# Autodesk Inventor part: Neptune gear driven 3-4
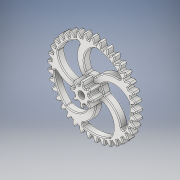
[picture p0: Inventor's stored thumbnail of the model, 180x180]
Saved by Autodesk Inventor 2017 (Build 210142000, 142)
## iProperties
Created: 2016-07
Part Number: Neptune gear driven 3-4
Material: Generic
Document SubType Name: Modeling
Designer: Stan
Density: 1 g/cm^3
Appearance: White
Author: Stan
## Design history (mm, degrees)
sketch "Sketch1" dims "d5" = 11.1125
  geometry: A1 r 17.728 centre (35.496, -7.809) between (28.667, -24.17) and (32.765, -25.326); A2 r 17.728 centre (35.496, -7.809) between (28.667, -24.17) and (32.765, -25.326); A3 r 17.728 centre (12.255, -34.216) between (29.283, -29.283) and (27.615, -25.365); A4 r 17.728 centre (12.255, -34.216) between (29.283, -29.283) and (27.615, -25.365); A5 r 17.728 centre (36.305, -1.698) between (32.339, -18.978) and (36.574, -19.425); A6 r 17.728 centre (36.305, -1.698) between (32.339, -18.978) and (36.574, -19.425); A7 r 17.728 centre (17.861, -31.653) between (33.811, -23.913) and (31.505, -20.333); A8 r 17.728 centre (17.861, -31.653) between (33.811, -23.913) and (31.505, -20.333); A9 r 17.728 centre (36.07, 4.462) between (35.082, -13.239) and (39.331, -12.964); A10 r 17.728 centre (36.07, 4.462) between (35.082, -13.239) and (39.331, -12.964); A11 r 17.728 centre (22.953, -28.179) between (37.366, -17.855) and (34.488, -14.716); A12 r 17.728 centre (22.953, -28.179) between (37.366, -17.855) and (34.488, -14.716); A13 r 17.728 centre (34.797, 10.493) between (36.814, -7.12) and (40.956, -6.131); A14 r 17.728 centre (34.797, 10.493) between (36.814, -7.12) and (40.956, -6.131); A15 r 17.728 centre (27.386, -23.895) between (39.846, -11.283) and (36.479, -8.676); A16 r 17.728 centre (27.386, -23.895) between (39.846, -11.283) and (36.479, -8.676); A17 r 17.728 centre (32.523, 16.223) between (37.488, -0.796) and (41.403, 0.879); A18 r 17.728 centre (32.523, 16.223) between (37.488, -0.796) and (41.403, 0.879); A19 r 17.728 centre (31.03, -18.923) between (41.179, -4.387) and (37.421, -2.386); A20 r 17.728 centre (31.03, -18.923) between (41.179, -4.387) and (37.421, -2.386); A21 r 17.728 centre (29.313, 21.486) between (37.083, 5.551) and (40.659, 7.863); A22 r 17.728 centre (29.313, 21.486) between (37.083, 5.551) and (40.659, 7.863); A23 r 17.728 centre (33.782, -13.407) between (41.328, 2.635) and (37.286, 3.972); A24 r 17.728 centre (33.782, -13.407) between (41.328, 2.635) and (37.286, 3.972); A25 r 17.728 centre (25.261, 26.131) between (35.612, 11.738) and (38.745, 14.622); A26 r 17.728 centre (25.261, 26.131) between (35.612, 11.738) and (38.745, 14.622); A27 r 17.728 centre (35.561, -7.505) between (40.289, 9.582) and (36.078, 10.216); A28 r 17.728 centre (35.561, -7.505) between (40.289, 9.582) and (36.078, 10.216); A29 r 17.728 centre (20.481, 30.024) between (33.116, 17.588) and (35.717, 20.959); A30 r 17.728 centre (20.481, 30.024) between (33.116, 17.588) and (35.717, 20.959); A31 r 17.728 centre (36.318, -1.387) between (38.09, 16.253) and (33.832, 16.167); A32 r 17.728 centre (36.318, -1.387) between (38.09, 16.253) and (33.832, 16.167); A33 r 17.728 centre (15.112, 33.054) between (29.667, 22.932) and (31.661, 26.694); A34 r 17.728 centre (15.112, 33.054) between (29.667, 22.932) and (31.661, 26.694); A35 r 17.728 centre (36.03, 4.771) between (34.795, 22.456) and (30.614, 21.652); A36 r 17.728 centre (36.03, 4.771) between (34.795, 22.456) and (30.614, 21.652); A37 r 17.728 centre (9.309, 35.132) between (25.365, 27.615) and (26.694, 31.661); A38 r 17.728 centre (9.309, 35.132) between (25.365, 27.615) and (26.694, 31.661); A39 r 17.728 centre (34.705, 10.791) between (30.499, 28.014) and (26.514, 26.514); A40 r 17.728 centre (34.705, 10.791) between (30.499, 28.014) and (26.514, 26.514); A41 r 17.728 centre (32.383, 16.501) between (25.326, 32.765) and (21.652, 30.614); A42 r 17.728 centre (32.383, 16.501) between (25.326, 32.765) and (21.652, 30.614); A43 r 17.728 centre (9.007, 35.211) between (-7.863, 40.659) and (-8.676, 36.479); A44 r 17.728 centre (-25.035, 26.347) between (-10.216, 36.078) and (-12.964, 39.331); A45 r 17.728 centre (2.927, 36.227) between (-14.622, 38.745) and (-14.716, 34.488); A46 r 17.728 centre (-29.128, 21.737) between (-16.167, 33.832) and (-19.425, 36.574); A47 r 17.728 centre (-3.238, 36.2) between (-20.959, 35.717) and (-20.333, 31.505); A48 r 17.728 centre (-32.383, 16.501) between (-21.652, 30.614) and (-25.326, 32.765); A49 r 17.728 centre (-9.309, 35.132) between (-26.694, 31.661) and (-25.365, 27.615); A50 r 17.728 centre (-34.705, 10.791) between (-26.514, 26.514) and (-30.499, 28.014); A51 r 17.728 centre (-15.112, 33.054) between (-31.661, 26.694) and (-29.667, 22.932); A52 r 17.728 centre (-36.03, 4.771) between (-30.614, 21.652) and (-34.795, 22.456); A53 r 17.728 centre (-20.481, 30.024) between (-35.717, 20.959) and (-33.116, 17.588); A54 r 17.728 centre (-36.318, -1.387) between (-33.832, 16.167) and (-38.09, 16.253); A55 r 17.728 centre (-25.261, 26.131) between (-38.745, 14.622) and (-35.612, 11.738); A56 r 17.728 centre (-35.561, -7.505) between (-36.078, 10.216) and (-40.289, 9.582); A57 r 17.728 centre (-29.313, 21.486) between (-40.659, 7.863) and (-37.083, 5.551); A58 r 17.728 centre (-33.782, -13.407) between (-37.286, 3.972) and (-41.328, 2.635); A59 r 17.728 centre (-32.523, 16.223) between (-41.403, 0.879) and (-37.488, -0.796); A60 r 17.728 centre (-31.03, -18.923) between (-37.421, -2.386) and (-41.179, -4.387); A61 r 17.728 centre (-34.797, 10.493) between (-40.956, -6.131) and (-36.814, -7.12); A62 r 17.728 centre (-27.386, -23.895) between (-36.479, -8.676) and (-39.846, -11.283); A63 r 17.728 centre (-36.07, 4.462) between (-39.331, -12.964) and (-35.082, -13.239); A64 r 17.728 centre (-22.953, -28.179) between (-34.488, -14.716) and (-37.366, -17.855)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; 1 further point
  constraints: 400 point on circle, 200 centre point, 4 horizontal alignment, 590 other
extrude "Extrusion1" new body sketch "Sketch1" distance "d0" = 6.35; taper "d1" = 0 deg
sketch "Sketch2"
  geometry: C1 r 3.175 at (0, 0); A1 r 6.91 centre (0, 0) between (-2.187, 6.554) and (-3.088, 6.181); A2 r 6.91 centre (0, 0) between (-6.181, 3.088) and (-6.554, 2.187); A3 r 6.91 centre (0, 0) between (-6.554, -2.187) and (-6.181, -3.088); A4 r 6.91 centre (0, 0) between (-3.088, -6.181) and (-2.187, -6.554); A5 r 6.91 centre (0, 0) between (2.187, -6.554) and (3.088, -6.181); A6 r 6.91 centre (0, 0) between (6.181, -3.088) and (6.554, -2.187); A7 r 6.91 centre (0, 0) between (6.554, 2.187) and (6.181, 3.088); A8 r 6.91 centre (0, 0) between (3.088, 6.181) and (2.187, 6.554); A9 r 12.44 centre (0, -1.866) between (0.976, 10.536) and (-0.976, 10.536); A10 r 7.658 centre (-6.013, 7.405) between (1.645, 7.316) and (0.976, 10.536); A11 r 7.658 centre (6.013, 7.405) between (-0.976, 10.536) and (-1.645, 7.305); A12 r 0.794 centre (2.438, 7.307) between (1.645, 7.316) and (2.187, 6.554); A13 r 0.794 centre (-2.438, 7.307) between (-2.187, 6.554) and (-1.645, 7.316); A14 r 12.44 centre (1.32, -1.32) between (-6.76, 8.14) and (-8.14, 6.76); A15 r 7.658 centre (-9.488, 0.984) between (-4.01, 6.336) and (-6.76, 8.14); A16 r 7.658 centre (-0.984, 9.488) between (-8.14, 6.76) and (-6.329, 4.003); A17 r 0.794 centre (-3.443, 6.891) between (-4.01, 6.336) and (-3.088, 6.181); A18 r 0.794 centre (-6.891, 3.443) between (-6.181, 3.088) and (-6.336, 4.01); A19 r 12.44 centre (1.866, 0) between (-10.536, 0.976) and (-10.536, -0.976); A20 r 7.658 centre (-7.405, -6.013) between (-7.316, 1.645) and (-10.536, 0.976); A21 r 7.658 centre (-7.405, 6.013) between (-10.536, -0.976) and (-7.305, -1.645); A22 r 0.794 centre (-7.307, 2.438) between (-7.316, 1.645) and (-6.554, 2.187); A23 r 0.794 centre (-7.307, -2.438) between (-6.554, -2.187) and (-7.316, -1.645); A24 r 12.44 centre (1.32, 1.32) between (-8.14, -6.76) and (-6.76, -8.14); A25 r 7.658 centre (-0.984, -9.488) between (-6.336, -4.01) and (-8.14, -6.76); A26 r 7.658 centre (-9.488, -0.984) between (-6.76, -8.14) and (-4.003, -6.329); A27 r 0.794 centre (-6.891, -3.443) between (-6.336, -4.01) and (-6.181, -3.088); A28 r 0.794 centre (-3.443, -6.891) between (-3.088, -6.181) and (-4.01, -6.336); A29 r 12.44 centre (0, 1.866) between (-0.976, -10.536) and (0.976, -10.536); A30 r 7.658 centre (6.013, -7.405) between (-1.645, -7.316) and (-0.976, -10.536); A31 r 7.658 centre (-6.013, -7.405) between (0.976, -10.536) and (1.645, -7.305); A32 r 0.794 centre (-2.438, -7.307) between (-1.645, -7.316) and (-2.187, -6.554); A33 r 0.794 centre (2.438, -7.307) between (2.187, -6.554) and (1.645, -7.316); A34 r 12.44 centre (-1.32, 1.32) between (6.76, -8.14) and (8.14, -6.76); A35 r 7.658 centre (9.488, -0.984) between (4.01, -6.336) and (6.76, -8.14); A36 r 7.658 centre (0.984, -9.488) between (8.14, -6.76) and (6.329, -4.003); A37 r 0.794 centre (3.443, -6.891) between (4.01, -6.336) and (3.088, -6.181); A38 r 0.794 centre (6.891, -3.443) between (6.181, -3.088) and (6.336, -4.01); A39 r 12.44 centre (-1.866, 0) between (10.536, -0.976) and (10.536, 0.976); A40 r 7.658 centre (7.405, 6.013) between (7.316, -1.645) and (10.536, -0.976); A41 r 7.658 centre (7.405, -6.013) between (10.536, 0.976) and (7.305, 1.645); A42 r 0.794 centre (7.307, -2.438) between (7.316, -1.645) and (6.554, -2.187); A43 r 0.794 centre (7.307, 2.438) between (6.554, 2.187) and (7.316, 1.645); A44 r 12.44 centre (-1.32, -1.32) between (8.14, 6.76) and (6.76, 8.14); A45 r 7.658 centre (0.984, 9.488) between (6.336, 4.01) and (8.14, 6.76); A46 r 7.658 centre (9.488, 0.984) between (6.76, 8.14) and (4.003, 6.329); A47 r 0.794 centre (6.891, 3.443) between (6.336, 4.01) and (6.181, 3.088); A48 r 0.794 centre (3.443, 6.891) between (3.088, 6.181) and (4.01, 6.336); 1 further point
  constraints: 104 point on circle, 49 centre point
  dimensions: "d7" = 6.35 diameter of C1
extrude "Extrusion2" join sketch "Sketch2" distance "d3" = 9.525; taper "d4" = 0 deg
fillet "Fillet4" dims "d9" = 0.79375
fillet "Fillet5" dims "d10" = 0.79375
fillet "Fillet6" dims "d11" = 0.79375
fillet "Fillet7" dims "d12" = 1.5875
fillet "Fillet8" dims "d13" = 1.5875
fillet "Fillet9" dims "d14" = 1.5875
fillet "Fillet10" dims "d15" = 0.79375
fillet "Fillet11" dims "d16" = 0.79375
fillet "Fillet12" dims "d17" = 0.79375
body "Solid1"
